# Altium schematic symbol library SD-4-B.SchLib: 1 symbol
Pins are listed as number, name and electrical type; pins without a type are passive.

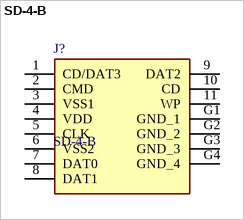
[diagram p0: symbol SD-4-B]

## SD-4-B
designator J?
Memory Card Connectors 11 Positions, Push In, Pull Out, SMT, 2.8 mm Height Above Board,; Manufacturer_Name: CUI Devices; Geometry.Height: 3.29mm
footprint SD4B
pins: 1 CD/DAT3, 2 CMD, 3 VSS1, 4 VDD, 5 CLK, 6 VSS2, 7 DAT0, 8 DAT1, 9 DAT2, 10 CD, 11 WP, G1 GND_1, G2 GND_2, G3 GND_3, G4 GND_4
